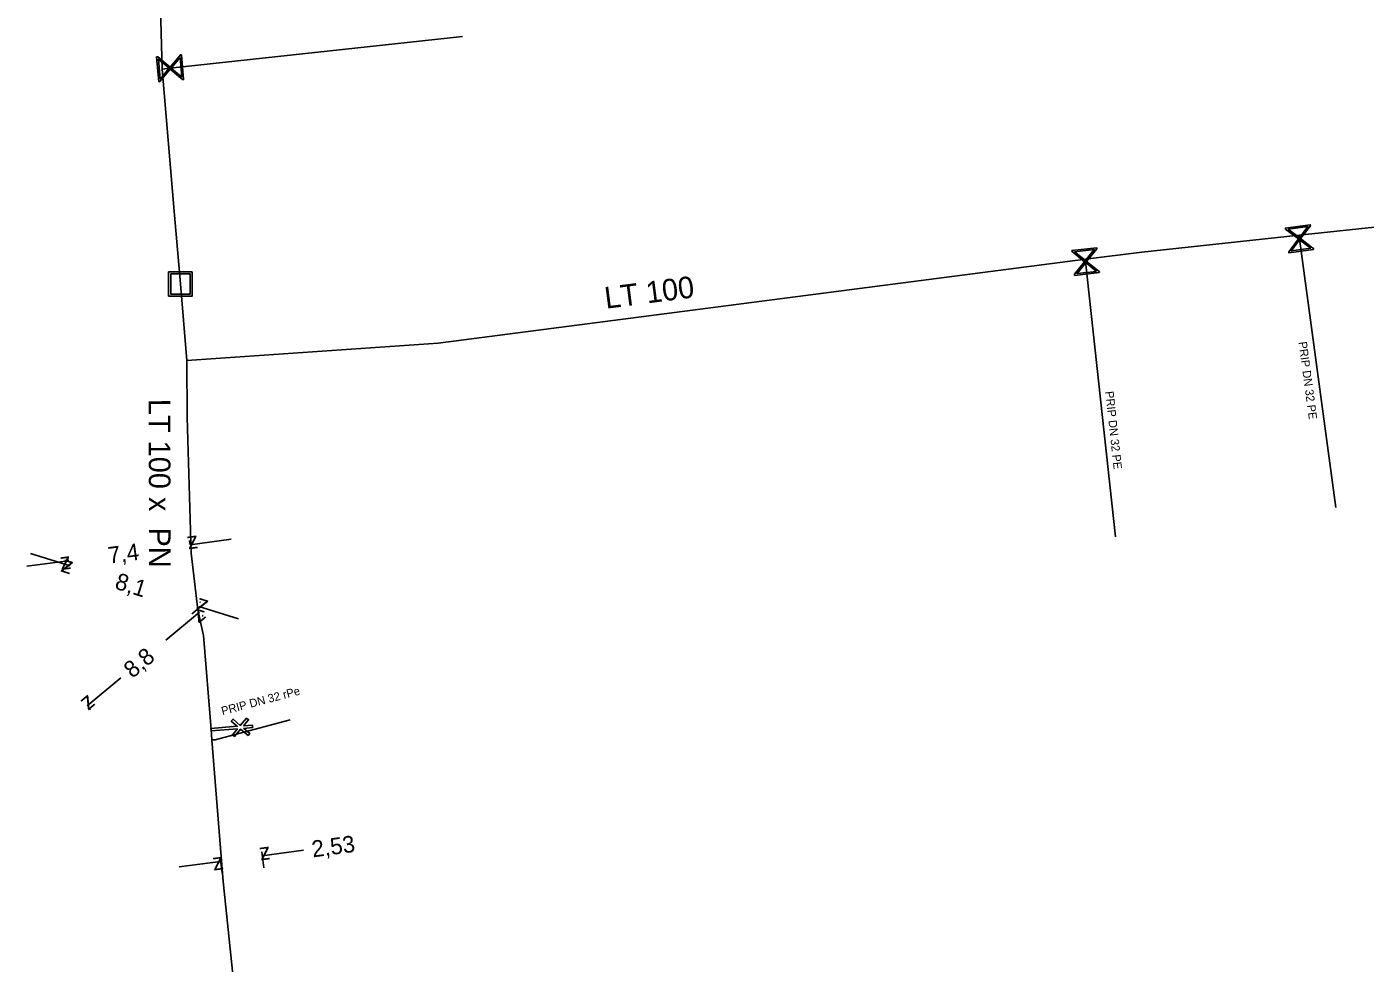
# Model space of a CAD drawing. Extents: x -643544 to -637295, y -1119190 to -1111715.
# Drawn here: x -642255.7 to -642175.2, y -1115322.4 to -1115266.1 of the extents above; entities that cross this region are included whole.
import ezdxf

# ---------------------------------------------------------------- set-up
doc = ezdxf.new("R2010")
doc.units = 0
for name, color, linetype in [('VP Kótování', 7, 'Continuous'), ('VP Popis přípojky', 7, 'Continuous'), ('VP Přípojka', 7, 'Continuous'), ('VP Změna profilu potrubí', 7, 'Continuous'), ('VP Řad', 7, 'Continuous'), ('VP Řad - popis', 7, 'Continuous'), ('VP Šachta', 7, 'Continuous'), ('VP Šoupě', 7, 'Continuous')]:
    doc.layers.add(name, color=color, linetype=linetype)

msp = doc.modelspace()

# ---------------------------------------------------------------- linework, layer by layer
at = {"layer": 'VP Kótování'}
for points in [[(-642245.87, -1115297.274), (-642245.905, -1115297.008)], [(-642243.394, -1115296.928), (-642245.872, -1115297.256)], [(-642255.457, -1115297.776), (-642253.073, -1115298.527)], [(-642253.206, -1115298.244), (-642253.241, -1115297.978)], [(-642255.686, -1115298.554), (-642253.208, -1115298.226)], [(-642252.99, -1115298.263), (-642252.998, -1115298.289)], [(-642247.322, -1115302.995), (-642245.299, -1115301.312)], [(-642242.962, -1115301.711), (-642245.347, -1115300.96)], [(-642245.264, -1115300.696), (-642245.272, -1115300.722)], [(-642245.094, -1115301.558), (-642245.139, -1115301.504)], [(-642250.041, -1115305.256), (-642252.065, -1115306.939)], [(-642251.86, -1115307.184), (-642251.905, -1115307.131)], [(-642241.436, -1115316.664), (-642241.565, -1115315.698)], [(-642239.053, -1115315.616), (-642241.532, -1115315.946)], [(-642246.518, -1115316.609), (-642244.04, -1115316.279)], [(-642243.944, -1115316.998), (-642244.072, -1115316.032)]]:
    msp.add_lwpolyline(points, dxfattribs=at)
at = {"layer": 'VP Přípojka'}
for points in [[(-642247.554, -1115268.681), (-642247.072, -1115268.632), (-642229.508, -1115266.719)], [(-642179.216, -1115278.663), (-642179.197, -1115278.876), (-642177.014, -1115295.027)], [(-642192.065, -1115280.113), (-642192.05, -1115280.25), (-642190.256, -1115296.78)], [(-642244.561, -1115308.987), (-642244.37, -1115308.97), (-642239.86, -1115307.77)]]:
    msp.add_lwpolyline(points, dxfattribs=at)
at = {"layer": 'VP Změna profilu potrubí'}
msp.add_lwpolyline([(-642242.663, -1115308.134), (-642242.125, -1115308.09), (-642242.113, -1115308.246), (-642242.646, -1115308.289), (-642242.288, -1115308.592), (-642242.39, -1115308.712), (-642242.834, -1115308.335), (-642243.208, -1115308.775), (-642243.326, -1115308.673), (-642243.025, -1115308.319), (-642244.605, -1115308.446), (-642244.617, -1115308.291), (-642243.035, -1115308.163), (-642243.394, -1115307.859), (-642243.292, -1115307.738), (-642242.852, -1115308.114), (-642242.475, -1115307.673), (-642242.356, -1115307.772), (-642242.663, -1115308.134)], dxfattribs=at)
at = {"layer": 'VP Řad'}
for points in [[(-642249.57, -1115234.49), (-642249.502, -1115235.448), (-642247.806, -1115259.192), (-642247.554, -1115268.681), (-642246.806, -1115277.452), (-642246.452, -1115281.593), (-642246.06, -1115286.192)], [(-642246.06, -1115286.192), (-642230.967, -1115285.144), (-642192.065, -1115280.113), (-642188.673, -1115279.674), (-642179.216, -1115278.663), (-642170.731, -1115277.756), (-642170.386, -1115277.719), (-642142.652, -1115273.774), (-642140.353, -1115273.447), (-642124.569, -1115271.639), (-642117.964, -1115270.64), (-642098.412, -1115267.961), (-642093.403, -1115268.557), (-642093.295, -1115268.568)], [(-642246.06, -1115286.192), (-642246.055, -1115289.6), (-642245.804, -1115297.769), (-642245.414, -1115301.173), (-642245.065, -1115302.715), (-642244.611, -1115308.367)], [(-642244.611, -1115308.367), (-642244.561, -1115308.987), (-642243.878, -1115317.494), (-642242.803, -1115327.892), (-642241.774, -1115338.347), (-642241.336, -1115341.358), (-642239.908, -1115355.307)]]:
    msp.add_lwpolyline(points, dxfattribs=at)
at = {"layer": 'VP Šachta'}
for points in [[(-642245.746, -1115280.871), (-642245.746, -1115282.322), (-642247.159, -1115282.322), (-642247.159, -1115280.871), (-642245.746, -1115280.871)], [(-642247.038, -1115280.994), (-642247.038, -1115282.199), (-642245.866, -1115282.199), (-642245.866, -1115280.994), (-642247.038, -1115280.994)]]:
    msp.add_lwpolyline(points, dxfattribs=at)
at = {"layer": 'VP Šoupě'}
for points in [[(-642246.39, -1115267.819), (-642246.259, -1115269.313), (-642246.325, -1115269.319), (-642246.421, -1115269.233), (-642247.065, -1115268.694), (-642247.688, -1115269.438), (-642247.753, -1115269.444), (-642247.885, -1115267.95), (-642247.819, -1115267.944), (-642247.076, -1115268.57), (-642246.537, -1115267.926), (-642246.456, -1115267.825), (-642246.39, -1115267.819)], [(-642247.673, -1115269.284), (-642247.132, -1115268.638), (-642247.778, -1115268.098), (-642247.673, -1115269.284)], [(-642246.47, -1115267.984), (-642247.008, -1115268.627), (-642246.366, -1115269.164), (-642246.47, -1115267.984)], [(-642178.353, -1115279.52), (-642179.84, -1115279.72), (-642179.848, -1115279.655), (-642179.767, -1115279.555), (-642179.259, -1115278.886), (-642180.031, -1115278.299), (-642180.04, -1115278.233), (-642178.553, -1115278.033), (-642178.544, -1115278.099), (-642179.135, -1115278.87), (-642178.467, -1115279.378), (-642178.362, -1115279.455), (-642178.353, -1115279.52)], [(-642179.876, -1115278.306), (-642179.205, -1115278.816), (-642178.696, -1115278.147), (-642179.876, -1115278.306)], [(-642191.223, -1115280.914), (-642192.715, -1115281.076), (-642192.722, -1115281.01), (-642192.638, -1115280.913), (-642192.112, -1115280.258), (-642192.869, -1115279.65), (-642192.876, -1115279.585), (-642191.385, -1115279.423), (-642191.378, -1115279.488), (-642191.989, -1115280.244), (-642191.333, -1115280.77), (-642191.23, -1115280.849), (-642191.223, -1115280.914)], [(-642192.715, -1115279.661), (-642192.057, -1115280.189), (-642191.531, -1115279.533), (-642192.715, -1115279.661)], [(-642178.522, -1115279.448), (-642179.189, -1115278.94), (-642179.695, -1115279.606), (-642178.522, -1115279.448)], [(-642191.39, -1115280.838), (-642192.044, -1115280.313), (-642192.567, -1115280.966), (-642191.39, -1115280.838)]]:
    msp.add_lwpolyline(points, dxfattribs=at)

# ---------------------------------------------------------------- texts
at = {"layer": 'VP Kótování'}
for s, rotation, p in [('7,4', 7.53728, (-642250.732, -1115298.403)), ('z', 187.53728, (-642245.442, -1115296.694)), ('z', 7.53728, (-642253.638, -1115298.788)), ('z', 342.51949, (-642253.7, -1115298.854)), ('8,1', 342.51949, (-642250.454, -1115299.876)), ('z', 162.51949, (-642244.72, -1115300.633)), ('z', 39.74871, (-642245.363, -1115302.016)), ('8,8', 39.74871, (-642249.337, -1115305.321)), ('z', 219.74871, (-642252, -1115306.235)), ('2,53', 7.58104, (-642238.492, -1115316.045)), ('z', 187.58104, (-642241.102, -1115315.384)), ('z', 7.58104, (-642244.469, -1115316.841))]:
    msp.add_text(s, height=1, rotation=rotation, dxfattribs=at).set_placement(p)
at = {"layer": 'VP Popis přípojky'}
for s, rotation, p in [('PRIP DN 32 PE', 277.66343, (-642179.255, -1115285.087)), ('PRIP DN 32 PE', 276.1927, (-642190.869, -1115288.059)), ('PRIP DN 32 rPe', 14.89988, (-642243.922, -1115307.504))]:
    msp.add_text(s, height=0.5, rotation=rotation, dxfattribs=at).set_placement(p)
at = {"layer": 'VP Řad - popis'}
for s, rotation, p in [('LT 100', 7.36888, (-642220.877, -1115283.085)), ('LT 100 x  PN ', 270.07869, (-642248.357, -1115288.493))]:
    msp.add_text(s, height=1.3, rotation=rotation, dxfattribs=at).set_placement(p)

doc.saveas('drawing.dxf')
